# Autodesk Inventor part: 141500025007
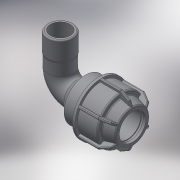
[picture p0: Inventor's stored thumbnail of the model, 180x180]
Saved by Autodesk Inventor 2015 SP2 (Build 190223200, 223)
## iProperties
Created: 2017-08
Part Number: 141500025007
Material: Generic
Description: L.14 90° ELBOW FEMALE ADAPTOR (SILVER) 25-3/4"
Document SubType Name: Modeling
Designer: KIM
Density: 1 g/cm^3
Appearance: Default
Author: KIM
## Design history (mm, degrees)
derived "141500.ipt"
feature "Solid1::141500.ipt"
feature "Solid2::141500.ipt"
tag "TaggingFeature1"
body "Solid1"
body "Solid2"
other parameters: "d1" = 25, "d2" = 48, "d4" = 15 deg, "d5" = 31.68, "d6" = 10.4544, "d16" = 25.5, "d17" = 2.4, "d24" = 2.4, "d25" = 45, "d26" = 37.5, "d27" = 2.4, "d28" = 135 deg, "d29" = 1.44, "d31" = 1.25, "d46" = 150 deg, "d49" = 2.5, "d50" = 0, "d58" = 0.75, "d61" = 360 deg, "d63" = 22.5, "d94" = 45, "d95" = 24.117, "d96" = 31.3521, "d97" = 18, "d98" = 19.2936, "d99" = 28.21689, "d100" = 135 deg, "d108" = 1.25, "d112" = 23.4, "d113" = 68, "d114" = 48.96, "d115" = 28.21689, "d116" = 45 deg, "d117" = 0, "d118" = 0, "d_" = 25, "G_" = 24.117, "A_" = 68, "l_" = 48, "l_2" = 18, "A_1" = 45
